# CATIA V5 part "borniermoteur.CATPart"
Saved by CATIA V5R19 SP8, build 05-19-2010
Part number: borniermoteur
Revision: ANY
Definition: UNKNOWN
Nomenclature: borniermoteur
Source: Unknown
Bounding box of the stored display mesh (mm): x -5.492 to 5.492, y -3 to 6, z -5.5 to 5.5
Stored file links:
  D:\Documents\1_Travail\1 - ac-limoges.fr\ac-limoges.fr\Emmanuel Maynard - STI2D_Turgot\2 -2I2D\2_SEQUENCE_Serrure_Biométrique\5-Spé_ITEC\Serrure_Bio_Eleve\borniermoteur.CATPart
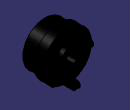
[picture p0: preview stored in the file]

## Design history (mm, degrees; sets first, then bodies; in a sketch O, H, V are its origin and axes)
Body1 "Enlèv. mat.-Extru.12" (main body)
  Solid1: solid without history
